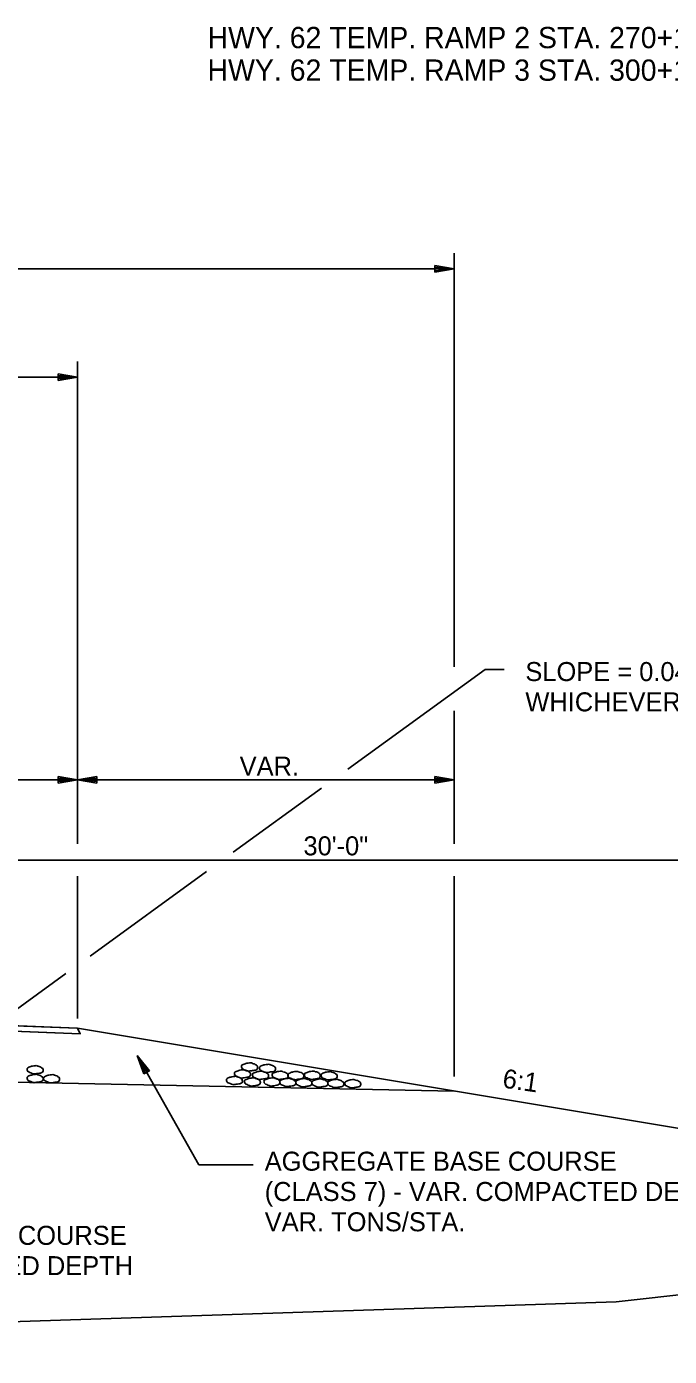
# Model space of a CAD drawing. Extents: x 1734743 to 1735935, y 759845 to 763831.
# Drawn here: x 1735769.47 to 1735789.41, y 762681.39 to 762722.64 of the extents above; entities that cross this region are included whole.
import ezdxf

# ---------------------------------------------------------------- set-up
doc = ezdxf.new("R2010")
doc.units = 0
for name, color, linetype in [('1', 7, 'Continuous'), ('19', 7, 'Continuous'), ('Level 1', 7, 'Continuous'), ('R_Prop Surface', 7, 'Continuous')]:
    doc.layers.add(name, color=color, linetype=linetype)

# ---------------------------------------------------------------- blocks, each defined once
blk = doc.blocks.new('ROCKS')
at = {"layer": '1'}
blk.add_spline([(0.013, 0.06), (0.053, 0.053), (0.107, 0.033), (0.133, 0.013), (0.133, -0.007), (0.12, -0.033), (0.107, -0.04), (0.073, -0.053), (0.033, -0.067), (0.013, -0.067), (-0.02, -0.06), (-0.06, -0.053), (-0.087, -0.047), (-0.113, -0.02), (-0.113, -0.007), (-0.107, 0.02), (-0.087, 0.033), (-0.067, 0.047), (-0.033, 0.053), (-0.02, 0.06), (0.013, 0.06)], degree=3, dxfattribs=at)

msp = doc.modelspace()

# ---------------------------------------------------------------- linework, layer by layer
at = {"layer": '19'}
for p, q in [((1735782.728, 762702.782), (1735782.728, 762715.61)), ((1735782.128, 762715.23), (1735782.128, 762715.02)), ((1735782.728, 762715.125), (1735782.128, 762715.23)), ((1735732.446, 762715.125), (1735782.728, 762715.125)), ((1735782.568, 762715.14), (1735782.128, 762715.175)), ((1735782.128, 762715.02), (1735782.728, 762715.125)), ((1735782.128, 762715.07), (1735782.568, 762715.11)), ((1735771.047, 762699.819), (1735771.046, 762712.254)), ((1735746.047, 762711.769), (1735771.046, 762711.769)), ((1735770.446, 762711.874), (1735770.446, 762711.664)), ((1735771.046, 762711.769), (1735770.446, 762711.874)), ((1735770.886, 762711.784), (1735770.446, 762711.819)), ((1735770.446, 762711.664), (1735771.046, 762711.769)), ((1735770.446, 762711.714), (1735770.886, 762711.754)), ((1735779.428, 762699.607), (1735783.691, 762702.701)), ((1735783.691, 762702.701), (1735784.284, 762702.701)), ((1735782.728, 762697.284), (1735782.728, 762701.414)), ((1735771.046, 762697.284), (1735771.047, 762699.819)), ((1735771.046, 762697.284), (1735771.047, 762699.819)), ((1735765.047, 762699.275), (1735771.047, 762699.275)), ((1735770.447, 762699.38), (1735770.447, 762699.17)), ((1735771.047, 762699.275), (1735770.447, 762699.38)), ((1735770.887, 762699.29), (1735770.447, 762699.325)), ((1735770.447, 762699.17), (1735771.047, 762699.275)), ((1735770.447, 762699.22), (1735770.887, 762699.26)), ((1735771.647, 762699.38), (1735771.047, 762699.275)), ((1735771.047, 762699.275), (1735782.728, 762699.274)), ((1735771.047, 762699.275), (1735771.647, 762699.17)), ((1735771.647, 762699.325), (1735771.207, 762699.29)), ((1735771.207, 762699.26), (1735771.647, 762699.22)), ((1735771.647, 762699.17), (1735771.647, 762699.38)), ((1735782.128, 762699.379), (1735782.128, 762699.169)), ((1735782.728, 762699.274), (1735782.128, 762699.379)), ((1735782.568, 762699.289), (1735782.128, 762699.324)), ((1735782.128, 762699.169), (1735782.728, 762699.274)), ((1735782.128, 762699.219), (1735782.568, 762699.259)), ((1735775.878, 762697.032), (1735778.618, 762699.02)), ((1735765.046, 762696.784), (1735795.041, 762696.782)), ((1735771.046, 762691.864), (1735771.046, 762696.284)), ((1735771.046, 762691.864), (1735771.046, 762696.284)), ((1735771.434, 762693.808), (1735775.048, 762696.43)), ((1735782.728, 762690.074), (1735782.728, 762696.284)), ((1735768.483, 762691.667), (1735770.684, 762693.264)), ((1735765.046, 762691.804), (1735771.046, 762691.564)), ((1735765.039, 762691.638), (1735771.131, 762691.394)), ((1735771.046, 762691.564), (1735795.046, 762687.562)), ((1735773.1, 762690.148), (1735772.897, 762690.721)), ((1735772.897, 762690.721), (1735773.282, 762690.25)), ((1735774.809, 762687.328), (1735772.897, 762690.721)), ((1735773.138, 762690.173), (1735772.962, 762690.574)), ((1735772.983, 762690.588), (1735773.233, 762690.228)), ((1735773.282, 762690.25), (1735773.1, 762690.148)), ((1735767.055, 762689.93), (1735782.73, 762689.615)), ((1735776.492, 762687.328), (1735774.809, 762687.328))]:
    msp.add_line(p, q, dxfattribs=at)
for points in [[(1735771.131, 762691.394), (1735765.131, 762691.634), (1735765.041, 762691.638), (1735749.964, 762691.94), (1735749.964, 762691.94), (1735749.964, 762691.94), (1735745.963, 762692.021), (1735746.046, 762692.186), (1735746.046, 762692.186), (1735750.046, 762692.105), (1735765.046, 762691.804), (1735771.046, 762691.564), (1735771.046, 762691.564), (1735771.131, 762691.394), (1735771.131, 762691.394), (1735771.131, 762691.394)], [(1735738.102, 762683.447), (1735746.995, 762684.106), (1735752.775, 762681.385), (1735767.375, 762682.404), (1735787.755, 762683.082), (1735799.985, 762684.441), (1735809.495, 762682.741), (1735820.81, 762685.178), (1735822.413, 762684.867)]]:
    msp.add_lwpolyline(points, dxfattribs=at)
at = {"layer": 'R_Prop Surface'}
msp.add_line((1735771.046, 762691.564), (1735771.131, 762691.394), dxfattribs=at)

# ---------------------------------------------------------------- block references
at = {"layer": 'Level 1', "xscale": 2.011654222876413}
for p, yscale, rotation in [((1735776.402, 762690.369), -2.011654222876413, 178.17361855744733), ((1735776.96, 762690.325), -2.011654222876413, 178.17361855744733), ((1735769.751, 762690.283), -2.0116542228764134, 177.95871721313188), ((1735769.751, 762690.012), -2.0116542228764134, 177.95871721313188), ((1735770.263, 762690.004), -2.0116542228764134, 177.95871721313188), ((1735775.933, 762689.95), -2.011654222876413, 178.17361855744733), ((1735776.184, 762690.155), -2.011654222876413, 178.17361855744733), ((1735776.491, 762689.906), -2.011654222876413, 178.17361855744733), ((1735776.742, 762690.111), -2.011654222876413, 178.17361855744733), ((1735777.099, 762689.906), -2.011654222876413, 178.17361855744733), ((1735777.35, 762690.111), -2.011654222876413, 178.17361855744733), ((1735777.589, 762689.889), -2.011654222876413, 178.17361855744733), ((1735777.843, 762690.104), -2.011654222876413, 178.17361855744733), ((1735778.085, 762689.882), -2.011654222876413, 178.17361855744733), ((1735778.35, 762690.112), -2.011654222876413, 178.17361855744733), ((1735778.87, 762690.096), -2.011654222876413, 178.17361855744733), ((1735778.581, 762689.871), -2.011654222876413, 178.17361855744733), ((1735779.081, 762689.858), -2.011654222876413, 178.17361855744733), ((1735779.603, 762689.851), -2.011654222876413, 178.17361855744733)]:
    msp.add_blockref('ROCKS', p, dxfattribs=dict(at, yscale=yscale, rotation=rotation))

# ---------------------------------------------------------------- texts
at = {"layer": '19'}
for s, height, rotation, p in [('HWY. 62 TEMP. RAMP 2 STA. 270+18.00 TO STA. 271+85.02', 0.65999, 359.9954, (1735775.079, 762721.974)), ('HWY. 62 TEMP. RAMP 3 STA. 300+12.00 TO STA. 300+66.36', 0.65999, 359.9954, (1735775.078, 762720.964)), ("SLOPE = 0.04' /' OR S.E. SLOPE", 0.59001, 360, (1735784.939, 762702.338)), ('WHICHEVER IS GREATER', 0.59001, 360, (1735784.939, 762701.398)), ('VAR.', 0.59, 359.9954, (1735776.076, 762699.403)), ('30\'-0"', 0.59, 359.9954, (1735778.055, 762696.931)), ('6:1', 0.59, 351.855, (1735784.205, 762689.729)), ('AGGREGATE BASE COURSE', 0.59001, 360, (1735776.853, 762687.147)), ('(CLASS 7) - VAR. COMPACTED DEPTH', 0.59001, 360, (1735776.853, 762686.207)), ('VAR. TONS/STA.', 0.59001, 360, (1735776.853, 762685.267)), ('15\'-0" AGGREGATE BASE COURSE', 0.59001, 360, (1735759.426, 762684.846)), ('(CLASS 7) - 7" COMPACTED DEPTH', 0.59001, 360, (1735759.426, 762683.906))]:
    msp.add_text(s, height=height, rotation=rotation, dxfattribs=at).set_placement(p)

doc.saveas('drawing.dxf')
